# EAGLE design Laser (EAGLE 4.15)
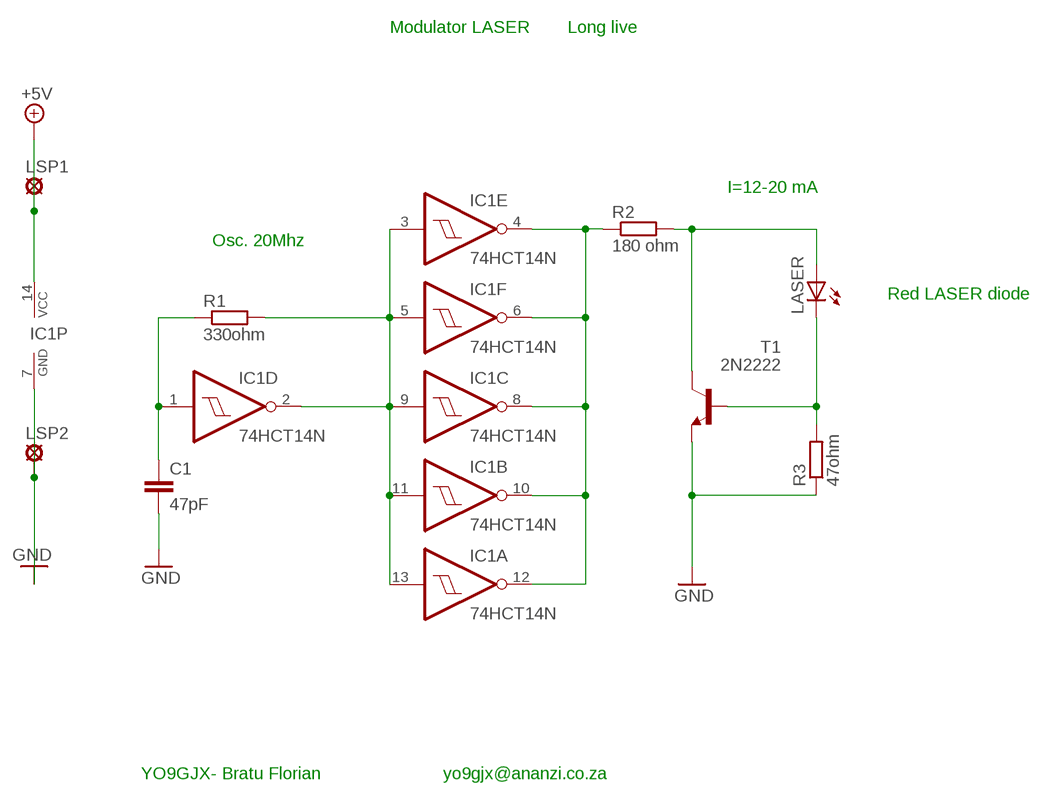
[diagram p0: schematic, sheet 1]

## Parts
C1  47pF  C-EU025-024X044  [C025-024X044]
IC1  74HCT14N  [DIL14]
LASER  LED5MM  [LED5MM]
LSP1  SE14  [SE14]
LSP2  SE14  [SE14]
R1  330ohm  R-EU_0204/5  [0204/5]
R2  180 ohm  R-EU_0204/5  [0204/5]
R3  47ohm  R-EU_0204/5  [0204/5]
T1  2N2222  [TO18]

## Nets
+5V: IC1.14(P:VCC) LSP1.MP
GND: C1.2 IC1.7(P:GND) LSP2.MP R3.1 T1.1(E)
N$1: C1.1 IC1.1(D:I) R1.1
N$2: IC1.2(D:O) IC1.3(E:I) IC1.5(F:I) IC1.9(C:I) IC1.11(B:I) IC1.13(A:I) R1.2
N$3: IC1.4(E:O) IC1.6(F:O) IC1.8(C:O) IC1.10(B:O) IC1.12(A:O) R2.1
N$4: LASER.A R2.2 T1.3(C)
N$5: LASER.K(C) R3.2 T1.2(B)

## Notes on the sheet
- Modulator LASER | Long live
- I=12-20 mA
- Osc. 20Mhz
- Red LASER diode
- YO9GJX- Bratu Florian | yo9gjx@ananzi.co.za

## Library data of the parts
C1 = rcl:C-EU: CAPACITOR, European symbol
IC1 = 74xx-eu:74*14: Hex schmitt trigger INVERTER
LASER = led:LED: LED
LSP1 LSP2 = solpad:SE14: SOLDER PAD
R1-R3 = rcl:R-EU_: RESISTOR, European symbol
T1 = transistor:2N2222: NPN TRANSISTOR

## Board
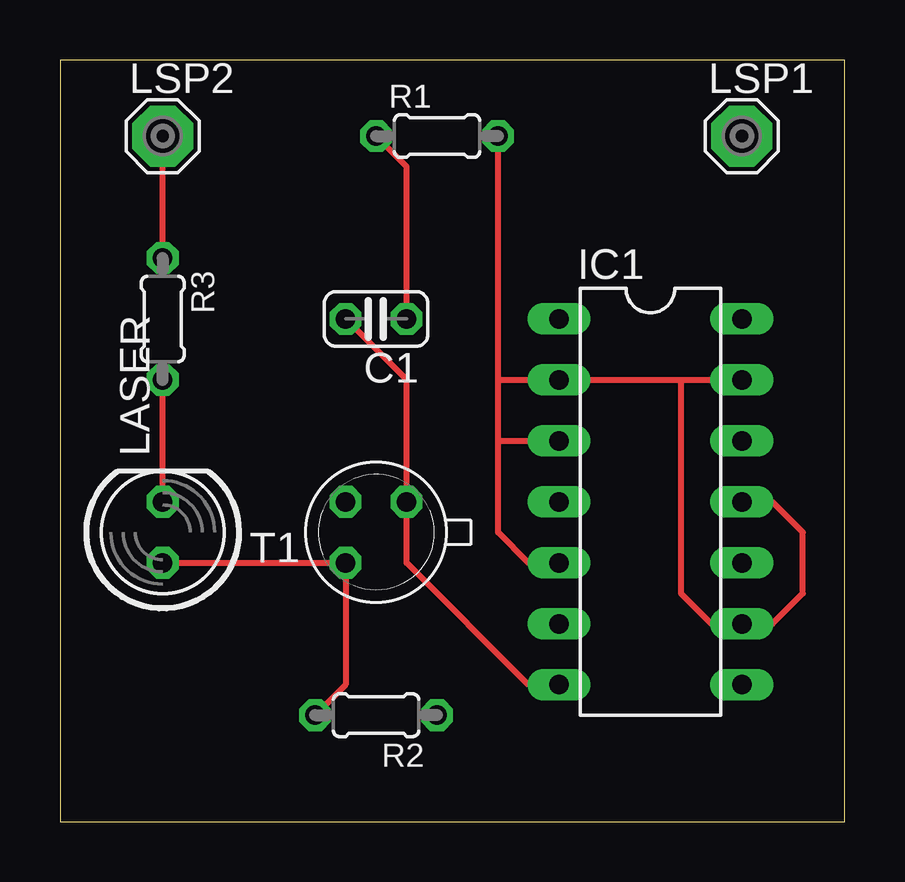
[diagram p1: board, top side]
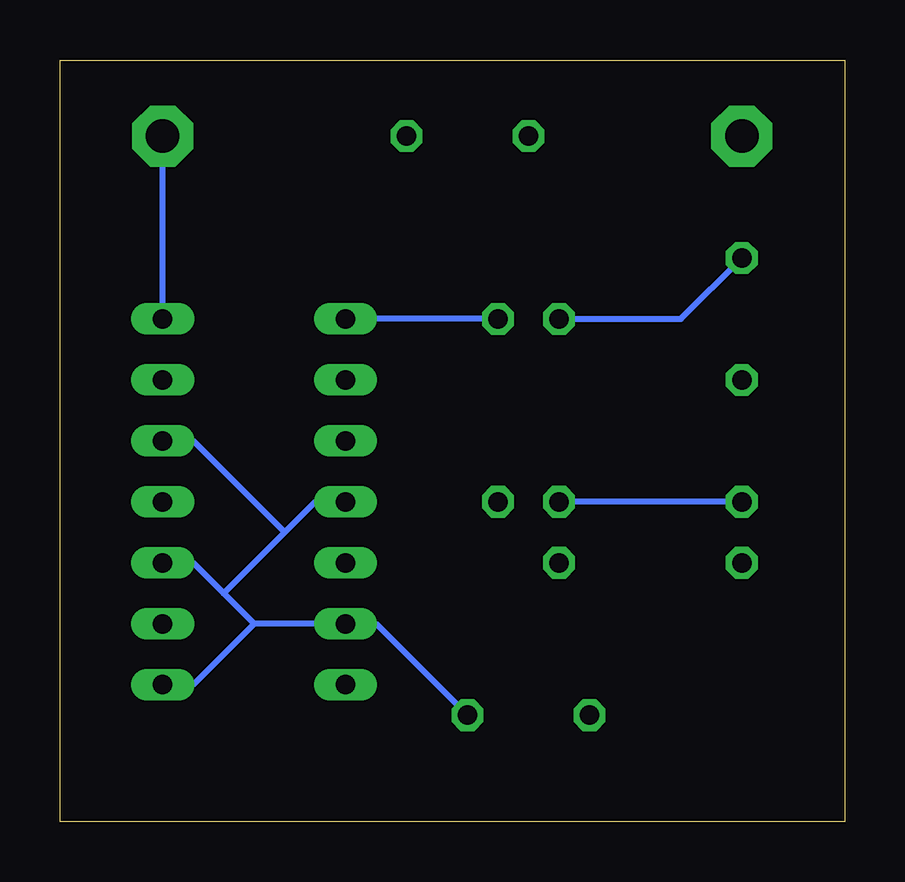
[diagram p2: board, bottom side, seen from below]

Size 32.69 x 31.74 mm. Coordinates in mm from the lower left corner, seen from the top.
Outline: 0,0 32.69,0 32.69,31.74 0,31.74 0,0
Copper layers (1*16): Top 0.035mm / dielectric 1.5mm / Bottom 0.035mm
Design rules "default": minimum track width 10mil, minimum drill 24mil, track to track 8mil, track to pad 8mil, pad to pad 8mil, via to via 8mil, smd to smd 8mil, copper to edge 40mil, drill to drill 8mil, minimum pad ring 10mil, minimum via ring 8mil, stop-mask expansion 4mil, vias tented up to drill 0mil, thermal gap 10mil

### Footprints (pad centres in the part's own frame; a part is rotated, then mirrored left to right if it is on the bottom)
C025-024X044 = drill 0.813 octagon: 1 -1.27,0; 2 1.27,0
DIL14 = drill 0.813 long: 1 -7.62,-3.81; 2 -5.08,-3.81; 3 -2.54,-3.81; 4 0,-3.81; 5 2.54,-3.81; 6 5.08,-3.81; 7 7.62,-3.81; 8 7.62,3.81; 9 5.08,3.81; 10 2.54,3.81; 11 0,3.81; 12 -2.54,3.81; 13 -5.08,3.81; 14 -7.62,3.81
LED5MM = drill 0.813 octagon: A -1.27,0; K 1.27,0
SE14 = drill 1.397 pad 2.54 octagon: MP 0,0
0204/5 = drill 0.813 octagon: 1 -2.54,0; 2 2.54,0
TO18 = drill 0.813 octagon: 1 -1.27,-1.27; 2 1.27,-1.27; 3 1.27,1.27

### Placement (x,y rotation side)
C1  13.17,20.95 180 top
IC1  24.6,13.33 270 top
LASER  4.28,12.06 90 top
LSP1  28.41,28.57 0 top
LSP2  4.28,28.57 0 top
R1  15.71,28.57 0 top
R2  13.17,4.44 180 top
R3  4.28,20.95 270 top
T1  13.17,12.06 180 top

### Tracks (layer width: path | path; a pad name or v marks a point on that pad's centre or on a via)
+5V
  Bottom 0.254: IC1.14 LSP1.MP
GND
  Top 0.254: R3.1 LSP2.MP | C1.2 14.44,18.41 T1.1 14.44,10.79 19.52,5.71 IC1.7
  Bottom 0.254: R3.1 6.82,20.95 C1.2
N$1
  Top 0.254: R1.1 14.44,27.3 C1.1
  Bottom 0.254: C1.1 IC1.1
N$2
  Top 0.254: IC1.11 29.68,13.33 30.95,12.06 30.95,9.52 29.68,8.25 IC1.9 27.14,8.25 25.87,9.52 25.87,18.41 | 18.25,18.41 R1.2 | 18.25,15.87 18.25,18.41 | 18.25,15.87 18.25,12.06 19.52,10.79 IC1.5 | 18.25,15.87 IC1.3 | 18.25,18.41 IC1.2 25.87,18.41 | 25.87,18.41 IC1.13
N$3
  Bottom 0.254: R2.1 19.52,8.25 IC1.6 24.6,8.25 | 24.6,8.25 27.14,5.71 IC1.8 | 24.6,8.25 25.87,9.52 | 25.87,9.52 27.14,10.79 IC1.10 | 25.87,9.52 23.33,12.06 | 23.33,12.06 22.06,13.33 IC1.4 | 23.33,12.06 27.14,15.87 IC1.12
N$4
  Top 0.254: R2.2 11.9,5.71 T1.3 LASER.A
N$5
  Top 0.254: LASER.K R3.2
  Bottom 0.254: LASER.K T1.2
